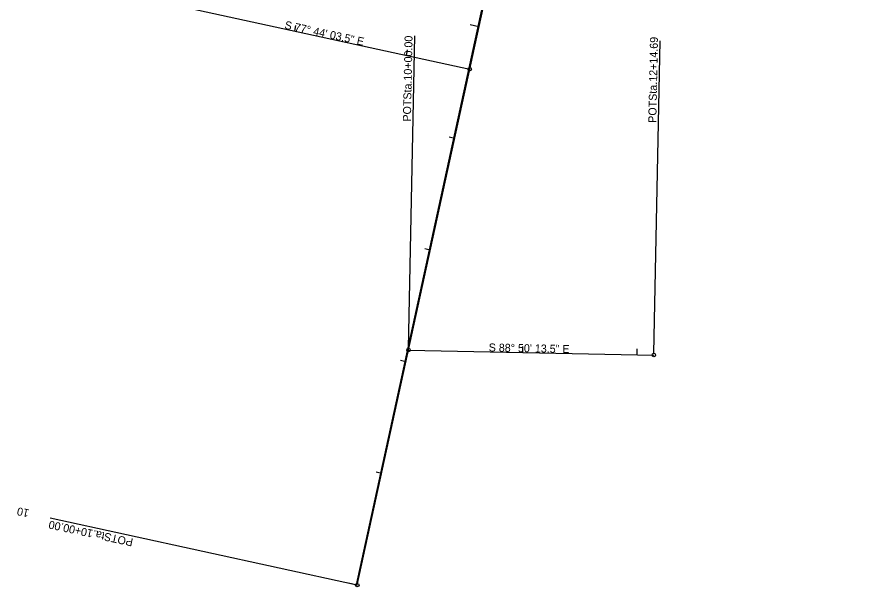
# Model space of a CAD drawing. Extents: x 1615740 to 1617154, y 899624 to 904812.
# Drawn here: x 1615891 to 1616642, y 899624 to 900122 of the extents above; entities that cross this region are included whole.
import ezdxf

# ---------------------------------------------------------------- set-up
doc = ezdxf.new("R2010")
doc.units = 0
for name, color, linetype in [('Default', 7, 'Continuous'), ('Exist Plan Preparation Drainage Flow Arrows', 7, 'Continuous'), ('Exist Plan Preparation Drainage Notes Label', 7, 'Continuous'), ('Exist Structure Minor Pipes CMP 15 Inch Text', 7, 'Continuous'), ('Exist Structure Minor Pipes CMP 24 Inch Text', 7, 'Continuous'), ('Exist Structure Minor Pipes RCP 12 Inch Text', 7, 'Continuous'), ('Prop Plan Preparation Sag', 7, 'Continuous'), ('Scratch_Level_7', 7, 'Continuous')]:
    doc.layers.add(name, color=color, linetype=linetype)

msp = doc.modelspace()

# ---------------------------------------------------------------- linework, layer by layer
at = {"layer": 'Default'}
for p, q in [((1616230.15, 899820.83), (1616641.95, 901715.87)), ((1616187.68, 899625.39), (1616607.18, 901555.86)), ((1616187.68, 899625.39), (1616542.07, 901256.25)), ((1616187.68, 899625.39), (1616542.07, 901256.25)), ((1616187.68, 899625.39), (1616542.07, 901256.25)), ((1616187.68, 899625.39), (1616542.07, 901256.25))]:
    msp.add_line(p, q, dxfattribs=at)
at = {"layer": 'Exist Plan Preparation Drainage Flow Arrows'}
for p, q in [((1616294.69, 900113.8), (1616286.87, 900115.5)), ((1616294.69, 900113.8), (1616286.87, 900115.5)), ((1616294.69, 900113.8), (1616286.87, 900115.5)), ((1616294.69, 900113.8), (1616286.87, 900115.5)), ((1616233.07, 899830.96), (1616233.23, 899838.95)), ((1616233.07, 899830.96), (1616233.23, 899838.95)), ((1616233.07, 899830.96), (1616233.23, 899838.95)), ((1616233.07, 899830.96), (1616233.23, 899838.95)), ((1616188.26, 899625.26), (1616180.44, 899626.96)), ((1616188.26, 899625.26), (1616180.44, 899626.96)), ((1616188.26, 899625.26), (1616180.44, 899626.96)), ((1616188.26, 899625.26), (1616180.44, 899626.96))]:
    msp.add_line(p, q, dxfattribs=at)
at = {"layer": 'Exist Plan Preparation Drainage Notes Label'}
for p, q in [((1616133.53, 900110), (1616134.59, 900114.89)), ((1616133.53, 900110), (1616134.59, 900114.89)), ((1616231.24, 900088.76), (1616232.31, 900093.64)), ((1616231.24, 900088.76), (1616232.31, 900093.64)), ((1616273.4, 900016.09), (1616268.52, 900017.16)), ((1616273.4, 900016.09), (1616268.52, 900017.16)), ((1616273.4, 900016.09), (1616268.52, 900017.16)), ((1616273.4, 900016.09), (1616268.52, 900017.16)), ((1616252.12, 899918.39), (1616247.23, 899919.45)), ((1616252.12, 899918.39), (1616247.23, 899919.45)), ((1616252.12, 899918.39), (1616247.23, 899919.45)), ((1616252.12, 899918.39), (1616247.23, 899919.45)), ((1616333.05, 899828.93), (1616333.15, 899833.92)), ((1616333.05, 899828.93), (1616333.15, 899833.92)), ((1616333.05, 899828.93), (1616333.15, 899833.92)), ((1616333.05, 899828.93), (1616333.15, 899833.92)), ((1616433.03, 899826.9), (1616433.13, 899831.89)), ((1616433.03, 899826.9), (1616433.13, 899831.89)), ((1616433.03, 899826.9), (1616433.13, 899831.89)), ((1616433.03, 899826.9), (1616433.13, 899831.89)), ((1616230.83, 899820.68), (1616225.94, 899821.74)), ((1616230.83, 899820.68), (1616225.94, 899821.74)), ((1616230.83, 899820.68), (1616225.94, 899821.74)), ((1616230.83, 899820.68), (1616225.94, 899821.74)), ((1616209.54, 899722.97), (1616204.66, 899724.03)), ((1616209.54, 899722.97), (1616204.66, 899724.03)), ((1616209.54, 899722.97), (1616204.66, 899724.03)), ((1616209.54, 899722.97), (1616204.66, 899724.03))]:
    msp.add_line(p, q, dxfattribs=at)
at = {"layer": 'Exist Structure Minor Pipes CMP 24 Inch Text'}
for p, q in [((1616188.26, 899625.26), (1616593.64, 901486.05)), ((1616035.81, 900131.25), (1616286.61, 900076.72)), ((1616233.07, 899830.96), (1616447.72, 899826.6))]:
    msp.add_line(p, q, dxfattribs=at)
at = {"layer": 'Exist Structure Minor Pipes RCP 12 Inch Text'}
msp.add_line((1616230.15, 899820.83), (1616641.93, 901715.79), dxfattribs=at)
at = {"layer": 'Prop Plan Preparation Sag'}
for p, q in [((1616286.93, 900078.19), (1616345.03, 900345.44)), ((1616286.93, 900078.19), (1616345.03, 900345.44)), ((1616233.1, 899832.45), (1616238.65, 900105.9)), ((1616233.1, 899832.45), (1616238.65, 900105.9)), ((1616233.1, 899832.45), (1616238.65, 900105.9)), ((1616233.1, 899832.45), (1616238.65, 900105.9)), ((1616447.75, 899828.1), (1616453.3, 900101.54)), ((1616447.75, 899828.1), (1616453.3, 900101.54)), ((1616447.75, 899828.1), (1616453.3, 900101.54)), ((1616447.75, 899828.1), (1616453.3, 900101.54)), ((1616186.79, 899625.58), (1615919.56, 899683.8)), ((1616186.79, 899625.58), (1615919.56, 899683.8)), ((1616186.79, 899625.58), (1615919.56, 899683.8)), ((1616186.79, 899625.58), (1615919.56, 899683.8))]:
    msp.add_line(p, q, dxfattribs=at)
for centre in [(1616286.61, 900076.72), (1616286.61, 900076.72), (1616233.07, 899830.96), (1616233.07, 899830.96), (1616233.07, 899830.96), (1616233.07, 899830.96), (1616447.72, 899826.6), (1616447.72, 899826.6), (1616447.72, 899826.6), (1616447.72, 899826.6), (1616188.26, 899625.26), (1616188.26, 899625.26), (1616188.26, 899625.26), (1616188.26, 899625.26)]:
    msp.add_circle(centre, 1.5, dxfattribs=at)

# ---------------------------------------------------------------- texts
at = {"layer": 'Exist Structure Minor Pipes CMP 15 Inch Text'}
for s, rotation, p in [('S 77%%d 44\' 03.5" E', 347.73429, (1616124.21, 900112.23)), ('S 77%%d 44\' 03.5" E', 347.73429, (1616124.21, 900112.23)), ('S 88%%d 50\' 13.5" E', 358.83708, (1616303.16, 899829.73)), ('S 88%%d 50\' 13.5" E', 358.83708, (1616303.16, 899829.73))]:
    msp.add_text(s, height=7, rotation=rotation, dxfattribs=at).set_placement(p)
at = {"layer": 'Prop Plan Preparation Sag'}
for s, rotation, p in [('POTSta.10+00.00', 88.83708, (1616235.13, 900030.78)), ('POTSta.10+00.00', 88.83708, (1616235.13, 900030.78)), ('POTSta.10+00.00', 88.83708, (1616235.13, 900030.78)), ('POTSta.10+00.00', 88.83708, (1616235.13, 900030.78)), ('POTSta.12+14.69', 88.83708, (1616449.84, 900029.73)), ('POTSta.12+14.69', 88.83708, (1616449.84, 900029.73)), ('POTSta.12+14.69', 88.83708, (1616449.84, 900029.73)), ('POTSta.12+14.69', 88.83708, (1616449.84, 900029.73)), ('POTSta.10+00.00', 167.70978, (1615992.58, 899665.84)), ('POTSta.10+00.00', 167.70978, (1615992.58, 899665.84)), ('POTSta.10+00.00', 167.70978, (1615992.58, 899665.84)), ('POTSta.10+00.00', 167.70978, (1615992.58, 899665.84))]:
    msp.add_text(s, height=7, rotation=rotation, dxfattribs=at).set_placement(p)
at = {"layer": 'Scratch_Level_7'}
msp.add_text('10', height=7, rotation=167.70978, dxfattribs=at).set_placement((1615901.6, 899691.29))
msp.add_text('10', height=7, rotation=167.70978, dxfattribs=at).set_placement((1615901.6, 899691.29))
msp.add_text('10', height=7, rotation=167.70978, dxfattribs=at).set_placement((1615901.6, 899691.29))
msp.add_text('10', height=7, rotation=167.70978, dxfattribs=at).set_placement((1615901.6, 899691.29))

doc.saveas('drawing.dxf')
